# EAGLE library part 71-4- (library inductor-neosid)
TRANSFORMER adjustable filter transformer
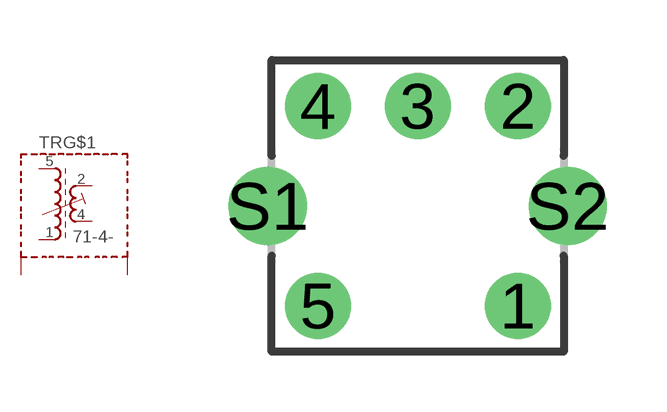
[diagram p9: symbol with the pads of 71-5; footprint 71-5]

Designator prefix TR; gates G$2=SHIELD3 G$1=SMF51-3

## 71-4-5124 (OC_FARNELL: unknown; OC_NEWARK: unknown)  [71-5]
1  G$1:E1  pas
2  G$1:A2  pas
4  G$1:E2  pas
5  G$1:A1  pas
S1  G$2:S1  pas
S2  G$2:S2  pas

## 71-4-4215 (OC_FARNELL: unknown; OC_NEWARK: unknown)  [71-5]
1  G$1:A2  pas
2  G$1:E1  pas
4  G$1:A1  pas
5  G$1:E2  pas
S1  G$2:S1  pas
S2  G$2:S2  pas

## 71-4-1542 (OC_FARNELL: unknown; OC_NEWARK: unknown)  [71-5]
1  G$1:A1  pas
2  G$1:A2  pas
4  G$1:E2  pas
5  G$1:E1  pas
S1  G$2:S1  pas
S2  G$2:S2  pas

## 71-4-2451 (OC_FARNELL: unknown; OC_NEWARK: unknown)  [71-5]
1  G$1:E2  pas
2  G$1:A1  pas
4  G$1:E1  pas
5  G$1:A2  pas
S1  G$2:S1  pas
S2  G$2:S2  pas

## 71-4-4251 (OC_FARNELL: unknown; OC_NEWARK: unknown)  [71-5]
1  G$1:E2  pas
2  G$1:E1  pas
4  G$1:A1  pas
5  G$1:A2  pas
S1  G$2:S1  pas
S2  G$2:S2  pas

## 71-4-2315 (OC_FARNELL: unknown; OC_NEWARK: unknown)  [71-5]
1  G$1:A2  pas
2  G$1:A1  pas
3  G$1:E1  pas
5  G$1:E2  pas
S1  G$2:S1  pas
S2  G$2:S2  pas

## 71-4-5142 (OC_FARNELL: unknown; OC_NEWARK: unknown)  [71-5]
1  G$1:E1  pas
2  G$1:E2  pas
4  G$1:A2  pas
5  G$1:A1  pas
S1  G$2:S1  pas
S2  G$2:S2  pas

## 71-4-5412 (OC_FARNELL: unknown; OC_NEWARK: unknown)  [71-5]
1  G$1:A2  pas
2  G$1:E2  pas
4  G$1:E1  pas
5  G$1:A1  pas
S1  G$2:S1  pas
S2  G$2:S2  pas

## 71-4-1524 (OC_FARNELL: unknown; OC_NEWARK: unknown)  [71-5]
Pads as for 71-5

## 71-4-2143 (OC_FARNELL: unknown; OC_NEWARK: unknown)  [71-5]
1  G$1:E1  pas
2  G$1:A1  pas
3  G$1:E2  pas
4  G$1:A2  pas
S1  G$2:S1  pas
S2  G$2:S2  pas

## 71-4-5123 (OC_FARNELL: unknown; OC_NEWARK: unknown)  [71-5]
1  G$1:E1  pas
2  G$1:A2  pas
3  G$1:E2  pas
5  G$1:A1  pas
S1  G$2:S1  pas
S2  G$2:S2  pas

## 71-4-5241 (OC_FARNELL: unknown; OC_NEWARK: unknown)  [71-5]
1  G$1:E2  pas
2  G$1:E1  pas
4  G$1:A2  pas
5  G$1:A1  pas
S1  G$2:S1  pas
S2  G$2:S2  pas

## 71-4-4512 (OC_FARNELL: unknown; OC_NEWARK: unknown)  [71-5]
1  G$1:A2  pas
2  G$1:E2  pas
4  G$1:A1  pas
5  G$1:E1  pas
S1  G$2:S1  pas
S2  G$2:S2  pas

## 71-4-1532 (OC_FARNELL: unknown; OC_NEWARK: unknown)  [71-5]
1  G$1:A1  pas
2  G$1:E2  pas
3  G$1:A2  pas
5  G$1:E1  pas
S1  G$2:S1  pas
S2  G$2:S2  pas

## 71-4-3254 (OC_FARNELL: unknown; OC_NEWARK: unknown)  [71-5]
2  G$1:E1  pas
3  G$1:A1  pas
4  G$1:E2  pas
5  G$1:A2  pas
S1  G$2:S1  pas
S2  G$2:S2  pas

## 71-4-2415 (OC_FARNELL: unknown; OC_NEWARK: unknown)  [71-5]
1  G$1:A2  pas
2  G$1:A1  pas
4  G$1:E1  pas
5  G$1:E2  pas
S1  G$2:S1  pas
S2  G$2:S2  pas

## Footprint 71-5 (pad centres in mm)
RF COIL ASSEMBLY 1 winding, 5 pads, grid 2.5 mm
drill 1.1 round: 1 2.5,-2.5; 2 2.5,2.5; 3 0,2.5; 4 -2.5,2.5; 5 -2.5,-2.5
drill 1.3 round: S1 -3.75,0; S2 3.75,0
